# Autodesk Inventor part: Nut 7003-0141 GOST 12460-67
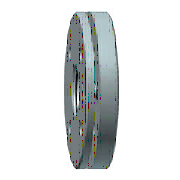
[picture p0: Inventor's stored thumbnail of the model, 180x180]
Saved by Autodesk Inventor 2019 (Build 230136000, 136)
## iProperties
Created: 2018-01
Part Number: Nut 7003-0141 GOST 12460-67
Material: Steel, Mild
Description: Nuts with lock screws
Document SubType Name: Modeling
Standard: GOST 12460-67
Designer: m.vorobev
Standards Organization: GOST
Language: en-US
Size Designation: 7003-0141
Categories: <MemberInstance><Categories><Category DisplayName="Fasteners" InternalName="e4da775c-781d-43d5-af7c-5136215cf5a6" Mnemonic="FSTN"><Category DisplayName="Nuts" I
Mass: 80.0051 g
Surface Area: 31.6673 cm^2
Volume: 10.1788 cm^3
Density: 7.85 g/cm^3
Appearance: Semi-Polished
IsCustomPart: 0
Title: Гайка
Author: m.vorobev
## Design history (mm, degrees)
sketch "Sketch1"
  geometry: L1 (0, -44.8)-(0, 44.8) reference; L2 (-44.8, 0)-(44.8, 0) reference; L3 (24.064, -24.064)-(-24.064, 24.064); L4 (23.945, 23.945)-(-23.945, -23.945); L5 (-2.93, 27.341)-(2.341, 22.07); L6 (-2.341, 27.93)-(2.93, 22.659); C1 r 32 at (0, 0); C2 r 2.5 at (0, 25); A1 r 24 centre (0, 0) between (-16.971, 16.971) and (16.971, 16.971); A2 r 3.75 centre (0, 25) between (-2.93, 27.341) and (2.341, 22.07); 3 further points
  constraints: 8 end point, 8 point on circle, 5 point on line, 4 centre point, 3 coincident, 2 midpoint, 1 parallel
  dimensions: "d0" = 64 diameter of C1 (= D_); "d3" = 48 diameter of A1 (= D_1); "d4" = 45 deg angle of L2 L4; "d5" = 45 deg angle of L2 L3; "d15" = 25 distance of point (0, 0) C2.centre (= A_); "d16" = 5 diameter of C2 (= d_2); "d49" = 45 deg angle of L1 L6; "d50" = 0.41667 distance from line of C2.centre L6 (= 0.0833333 x d_2); "d51" = 0.41667 distance from line of C2.centre L5 (= d50); "d54" = 7.5 diameter of A2 (= 1.5 x d_2)
extrude "Extrusion1" new body sketch "Sketch1" distance "d6" = 12 (= H_); taper "d7" = 0 deg
hole "Hole1" sketch "Sketch1" diameter "d8" = 4.5 (= d_1s); stored, may be unused: countersink angle "d12" = 90 deg, drill point angle "d14" = 118 deg; dims "d9" = 6, "d10" = 4, "d11" = 2, "d13" = 7 (= h_1)
extrude "Extrusion2" cut sketch "Sketch1" distance "d17" = 0.05; taper "d18" = 0 deg
hole "Hole2" diameter "d27" = 34.3762; stored, may be unused: countersink angle "d31" = 90 deg, drill point angle "d33" = 118 deg; dims "d25" = 10, "d26" = 10, "d28" = 6, "d29" = 4, "d30" = 2, "d32" = 8
workplane "Work Plane1"
sketch "Sketch3"
  geometry: L1 (-32, 12)-(32, 12) reference; L2 (-32, 0)-(32, 0) reference; L3 (-32, 0)-(-32, 12) reference; L4 (32, 0)-(32, 12) reference; L5 (-32, 3)-(32, 3); L6 (-32, 4.6)-(32, 4.6); 1 further point
  constraints: 4 end point, 4 point on line, 1 parallel, 1 perpendicular
  dimensions: "d35" = 1.6 distance between parallel lines of L5 L6; "d36" = 3 distance between parallel lines of L2 L5 (= h_s)
extrude "Extrusion4" cut sketch "Sketch3" extent not by distance; stored distance "d37" = 10; taper "d38" = 0 deg
extrude "Extrusion5" join sketch "Sketch1" stored distance "d39" = 10; taper "d40" = 0 deg
thread "Thread1" dims "d55" = 10, "d56" = 0
chamfer "Chamfer1" distance "d57" = 0.5; stored, may be unused: second distance "d58" = 2, angle "d59" = 45 deg
body "Solid1"
extrude "Extrusion3" cut sketch "Sketch1" extent not by distance; stored distance "d52" = 10; taper "d53" = -45 deg
node "Projected Loop2"
other parameters: "D_" = 64 [user parameter; used in 2 equation terms], "d" = 36 [user parameter], "H_" = 12 [user parameter; used in 1 equation term], "D_1" = 48 [user parameter; used in 1 equation term], "d_1s" = 4.5 [user parameter; used in 1 equation term], "d_2" = 5 [user parameter; used in 3 equation terms], "A_" = 25 [user parameter; used in 1 equation term], "l_" = 38 [user parameter; used in 1 equation term], "h_s" = 3 [user parameter; used in 1 equation term], "h_1" = 7 [user parameter; used in 1 equation term], "d34" = -6 (= -l_ + 0.5 x D_), "d60" = 0, "d61" = 0, "d62" = 0, "d63" = 0
